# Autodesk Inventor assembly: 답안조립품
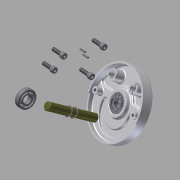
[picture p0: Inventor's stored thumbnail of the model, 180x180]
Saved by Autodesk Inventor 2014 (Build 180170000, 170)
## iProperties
Created: 2015-06
Part Number: 답안조립품
Document SubType Name: Assembly
Designer: MYHOME
Author: MYHOME
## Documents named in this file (8)
- C:\Documents and Settings\MYHOME\바탕 화면\450631V1035\답안조립품.iam
- C:\Documents and Settings\MYHOME\바탕 화면\450631V1035\덮개.ipt
- C:\Documents and Settings\MYHOME\바탕 화면\450631V1035\베어링62_22.ipt
- C:\Documents and Settings\MYHOME\바탕 화면\450631V1035\본체.ipt
- C:\Documents and Settings\MYHOME\바탕 화면\450631V1035\축.ipt
- C:\Documents and Settings\MYHOME\바탕 화면\450631V1035\멈춤링.ipt
- C:\Documents and Settings\MYHOME\바탕 화면\450631V1035\M10x35.ipt
- C:\Documents and Settings\MYHOME\바탕 화면\450631V1035\평행핀.ipt
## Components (10 placed, 4 different names)
1. KS B 2023 62/22 - 22 x 50 x 14:1
2. KS B 1336 22 x 1.2:1
3. KS B 1336 22 x 1.2:2
4. KS B 1003 - 미터 M 10 x 35:1
5. KS B 1003 - 미터 M 10 x 35:2
6. KS B 1003 - 미터 M 10 x 35:3
7. KS B 1003 - 미터 M 10 x 35:4
8. KS B 1320 B B 5 x  20:1
9. KS B 1320 B B 5 x  20:2
10. KS B 2023 62/22 - 22 x 50 x 14:2
